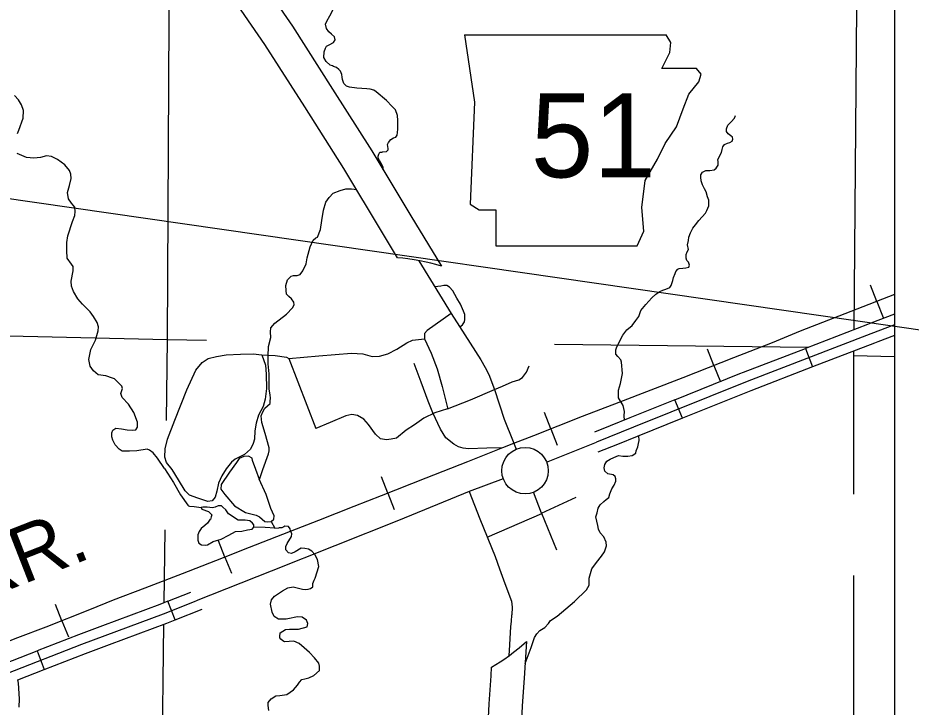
# Model space of a CAD drawing. Extents: x 8749 to 11879, y 13275 to 15339.
# Drawn here: x 10827.5 to 10962.2, y 13800.6 to 13904.5 of the extents above; entities that cross this region are included whole.
import ezdxf

# ---------------------------------------------------------------- set-up
doc = ezdxf.new("R2010")
doc.units = 0
for name, color, linetype in [('Level 10', 7, 'Continuous'), ('Level 21', 7, 'Continuous'), ('Level 22', 7, 'Continuous'), ('Level 24', 7, 'Continuous'), ('Level 31', 7, 'Continuous'), ('Level 32', 7, 'Continuous'), ('Level 35', 7, 'Continuous'), ('Level 4', 7, 'Continuous'), ('Level 40', 7, 'Continuous'), ('Level 5', 7, 'Continuous'), ('R_Draft', 7, 'Continuous')]:
    doc.layers.add(name, color=color, linetype=linetype)

msp = doc.modelspace()

# ---------------------------------------------------------------- linework, layer by layer
at = {"layer": 'Level 10'}
for points in [[(10863.29, 13911.43), (10868.9, 13903.24), (10874.98, 13893.76), (10880.91, 13884.42), (10886.77, 13874.66), (10891.41, 13867.06)], [(10884.78, 13868.31), (10882.49, 13872.07), (10876.65, 13881.8), (10870.77, 13891.08), (10864.73, 13900.47), (10859.16, 13908.61)], [(10891.41, 13867.06), (10890.52, 13867.31), (10889.81, 13867.49), (10889.08, 13867.66), (10888.14, 13867.85), (10887.28, 13868), (10886.33, 13868.14), (10885.54, 13868.24), (10884.78, 13868.31)], [(10887.98, 13867.88), (10892.85, 13859.9), (10894.12, 13857.97), (10897.32, 13852.91), (10897.97, 13851.76), (10898.52, 13850.74), (10899.41, 13848.44), (10900.85, 13843.99), (10902.2, 13840.61), (10902.47, 13839.98), (10902.68, 13839.46)], [(10900.72, 13835), (10895.59, 13833.08)], [(10895.59, 13833.08), (10897.18, 13828.98), (10899.49, 13823.3), (10900.14, 13821.45), (10900.74, 13819.78), (10901.26, 13818.4), (10901.95, 13816.57), (10902.07, 13815.66), (10902, 13814.51)], [(10901.58, 13808.33), (10901.68, 13809.97), (10901.86, 13812.73), (10901.94, 13813.49), (10902, 13814.51)], [(10898.96, 13806.6), (10899.61, 13807.01), (10900.26, 13807.42), (10900.79, 13807.78), (10901.63, 13808.37), (10902.28, 13808.87), (10903.09, 13809.51), (10904.22, 13810.47)], [(10904.22, 13810.47), (10903.86, 13804.97), (10903.58, 13800.79), (10903.29, 13794.78), (10903.08, 13790.3), (10902.9, 13782.42), (10902.8, 13776.62)], [(10897.8, 13776.71), (10897.9, 13782.52), (10898.09, 13790.48), (10898.3, 13795.02), (10898.59, 13801.08), (10898.87, 13805.3), (10898.96, 13806.6)]]:
    msp.add_lwpolyline(points, dxfattribs=at)
at = {"layer": 'Level 21'}
for p, q in [((10894.86, 13901.94), (10896.39, 13891.79)), ((10925.99, 13900.76), (10925.29, 13901.93)), ((10925.82, 13899.24), (10925.99, 13900.76)), ((10924.64, 13896.87), (10925.82, 13899.24)), ((10929.88, 13896.87), (10924.64, 13896.87)), ((10930.56, 13896.02), (10929.88, 13896.87)), ((10930.22, 13894.84), (10930.56, 13896.02)), ((10928.7, 13892.98), (10930.22, 13894.84)), ((10927.85, 13890.78), (10928.7, 13892.98)), ((10896.39, 13891.79), (10895.71, 13876.4)), ((10926.84, 13888.07), (10927.85, 13890.78)), ((10925.15, 13885.53), (10926.84, 13888.07)), ((10923.96, 13883.16), (10925.15, 13885.53)), ((10922.1, 13879.95), (10923.96, 13883.16)), ((10921.59, 13875.89), (10922.1, 13879.95)), ((10895.71, 13876.4), (10897.06, 13875.55)), ((10897.06, 13875.55), (10899.6, 13875.55)), ((10899.6, 13875.55), (10899.6, 13870.14)), ((10921.93, 13872.34), (10921.59, 13875.89)), ((10920.92, 13870.14), (10921.93, 13872.34)), ((10899.6, 13870.14), (10920.92, 13870.14))]:
    msp.add_line(p, q, dxfattribs=at)
msp.add_lwpolyline([(10894.86, 13901.94), (10925.29, 13901.93)], dxfattribs=at)
at = {"layer": 'Level 22'}
msp.add_lwpolyline([(10959.72, 13858.22), (10956.18, 13856.86), (10937.5, 13849.67), (10920.37, 13842.78), (10914.78, 13840.54)], dxfattribs=at)
at = {"layer": 'Level 24'}
msp.add_circle((10904, 13836.22), 3.5, dxfattribs=at)
at = {"layer": 'Level 31'}
for p, q in [((10946.28, 13854.66), (10947.36, 13851.86)), ((10927.73, 13844.12), (10926.61, 13846.91)), ((10851.23, 13813.74), (10850.13, 13816.53)), ((10850.13, 13816.53), (10850.13, 13816.53)), ((10830.39, 13809.05), (10831.47, 13806.25))]:
    msp.add_line(p, q, dxfattribs=at)
for points in [[(10959.72, 13859.82), (10956.14, 13858.45)], [(10956.14, 13858.45), (10955.64, 13858.26), (10946.28, 13854.66)], [(10959.72, 13856.61), (10957.21, 13855.65)], [(10957.21, 13855.65), (10956.72, 13855.46), (10947.36, 13851.86)], [(10936.41, 13850.85), (10936.95, 13851.06), (10946.28, 13854.66)], [(10926.61, 13846.91), (10936.41, 13850.85)], [(10947.36, 13851.86), (10938.05, 13848.27), (10937.53, 13848.06)], [(10926.61, 13846.91), (10919.82, 13844.17), (10916.82, 13842.97)], [(10937.53, 13848.06), (10927.73, 13844.12)], [(10927.73, 13844.12), (10920.93, 13841.39), (10917.93, 13840.19)], [(10916.82, 13842.97), (10914.5, 13842.04)], [(10907.25, 13837.52), (10914.78, 13840.54)], [(10917.93, 13840.19), (10914.99, 13839.01)], [(10895.59, 13833.08), (10884.89, 13828.72), (10865.69, 13821.07), (10854.39, 13816.6)], [(10906.49, 13829.81), (10905.27, 13832.96)], [(10898.31, 13826.2), (10906.51, 13829.76)], [(10850.13, 13816.53), (10853.57, 13817.89)], [(10825.81, 13805.66), (10837.15, 13810.07), (10849.45, 13814.65), (10854.39, 13816.6)], [(10850.13, 13816.53), (10848.91, 13816.05), (10840.27, 13812.83)], [(10851.23, 13813.74), (10855.28, 13815.34)], [(10841.32, 13810.02), (10849.99, 13813.25), (10851.23, 13813.74)], [(10840.27, 13812.83), (10836.62, 13811.47), (10830.39, 13809.05)], [(10824.71, 13800.69), (10824.75, 13801.81), (10824.63, 13803.82), (10824.1, 13806.61), (10830.39, 13809.05)], [(10831.47, 13806.25), (10837.68, 13808.67), (10841.32, 13810.02)], [(10827.71, 13800.58), (10827.75, 13801.85), (10827.61, 13804.19), (10827.51, 13804.71), (10831.47, 13806.25)]]:
    msp.add_lwpolyline(points, dxfattribs=at)
at = {"layer": 'Level 32'}
for points in [[(10894.14, 13857.93), (10894.56, 13858.22), (10894.85, 13858.64), (10894.92, 13859.02), (10894.9, 13859.77), (10894.74, 13860.28), (10894.28, 13861.33), (10893.72, 13862.22), (10893.12, 13863.31), (10892.61, 13863.91), (10892.21, 13864.13), (10891.77, 13864.13), (10891.3, 13864.02), (10890.38, 13863.95)], [(10892.85, 13859.9), (10889.25, 13857.38), (10888.85, 13856.89), (10888.81, 13856.09), (10889.83, 13853.96), (10890.76, 13851.56), (10891.52, 13848.89), (10892.36, 13845.51)], [(10868.39, 13853.13), (10872.87, 13853.53), (10877.8, 13853.93), (10879.54, 13853.84), (10880.96, 13853.44), (10882.07, 13853.49), (10883.28, 13853.86), (10884.64, 13854.55), (10886.15, 13855.49), (10887, 13855.89), (10887.93, 13855.98), (10888.81, 13856.09)], [(10864.3, 13853.7), (10864.83, 13852.15), (10864.97, 13850.77), (10865.01, 13848.6), (10864.79, 13847), (10864.48, 13845.88), (10863.77, 13844.59), (10863.46, 13843.39), (10863.23, 13842.24), (10863.19, 13840.95), (10863.01, 13840.33), (10862.61, 13839.48), (10861.68, 13838.64), (10860.3, 13837.97), (10859.73, 13837.53), (10858.93, 13836.5), (10858.26, 13835.44), (10857.77, 13834.32), (10857.51, 13833.12), (10857.24, 13832.23), (10856.79, 13831.66), (10856.17, 13831.57), (10854.62, 13832.06), (10853.37, 13832.55), (10852.71, 13833.21), (10851.73, 13834.86), (10850.75, 13836.41), (10849.91, 13837.44), (10849.69, 13838.28), (10849.73, 13839.53), (10850.09, 13840.99), (10851.15, 13843.84), (10852.97, 13848.42), (10854.35, 13851.4), (10855.28, 13852.51), (10856.22, 13853.13), (10857.46, 13853.44), (10858.93, 13853.71), (10861.1, 13853.8), (10863.01, 13853.84), (10864.3, 13853.7)], [(10864.3, 13853.7), (10866.3, 13853.58), (10868.03, 13853.35), (10868.39, 13853.13), (10871.1, 13846.11), (10872.42, 13842.59)], [(10899.41, 13848.44), (10900.62, 13848.96), (10902.08, 13849.6), (10903.06, 13849.94), (10903.61, 13850.28), (10904.2, 13851.08), (10904.64, 13852.04)], [(10892.32, 13845.54), (10895.78, 13846.89), (10899.41, 13848.44)], [(10892.32, 13845.54), (10890.41, 13844.95), (10888.75, 13844.12), (10887.34, 13843.13), (10886.06, 13842.33), (10884.59, 13841.13), (10883.79, 13840.95), (10883.08, 13840.86), (10882.19, 13841.04), (10881.44, 13841.75), (10880.37, 13843.17), (10879.66, 13843.97), (10878.73, 13844.55), (10877.88, 13844.68), (10876.99, 13844.51), (10874.6, 13843.48), (10872.42, 13842.59)], [(10906.49, 13829.8), (10911.71, 13832.21)], [(10906.49, 13829.8), (10908.75, 13824.3)]]:
    msp.add_lwpolyline(points, dxfattribs=at)
at = {"layer": 'Level 35'}
for points in [[(10874.43, 13900.41), (10875.11, 13900.77), (10875.34, 13901.17), (10875.26, 13901.6), (10874.81, 13902.01), (10874.38, 13902.36), (10874.03, 13902.89), (10873.92, 13903.55), (10874.08, 13904.01), (10874.53, 13904.81), (10875.11, 13905.85), (10875.84, 13906.79), (10876.85, 13908.18), (10877.11, 13908.76), (10877.18, 13909.34)], [(10884.79, 13887.72), (10884.81, 13889.03), (10884.74, 13889.76), (10884.46, 13890.62), (10883.95, 13891.1), (10883.12, 13892.04), (10881.55, 13893.33), (10881.17, 13893.58), (10880.62, 13893.76), (10880.14, 13893.81), (10878.62, 13893.91), (10877.51, 13894.03), (10877.08, 13894.21), (10876.65, 13894.59), (10876.48, 13895.17), (10876.43, 13895.53), (10876.37, 13895.93), (10876.17, 13896.44), (10875.9, 13896.69), (10875.57, 13897.02), (10875.12, 13897.13), (10874.94, 13897.25), (10874.58, 13897.37), (10873.98, 13897.9), (10873.67, 13898.53), (10873.7, 13899.34), (10873.9, 13899.9), (10874.05, 13900.2), (10874.43, 13900.41)], [(10827.46, 13887.04), (10827.63, 13887.55), (10828.32, 13889.37), (10828.34, 13890.54), (10828.04, 13891.37), (10827.58, 13892.13), (10827, 13892.77)], [(10934.06, 13885.39), (10934.54, 13885.58), (10934.89, 13885.69), (10935.22, 13885.89), (10935.34, 13886.19), (10935.29, 13886.49), (10935.04, 13886.72), (10934.64, 13887), (10934.41, 13887.35), (10934.36, 13887.76), (10934.61, 13888.29), (10935.09, 13888.8), (10935.57, 13889.35), (10935.72, 13889.78)], [(10882.38, 13882.36), (10882.03, 13882.97), (10881.83, 13883.35), (10881.83, 13883.65), (10881.93, 13883.93), (10882.08, 13884.26), (10882.46, 13884.26), (10882.51, 13884.28), (10883.09, 13884.33), (10883.37, 13884.61), (10883.37, 13884.81), (10883.32, 13885.09), (10883.27, 13885.4), (10883.4, 13885.72), (10883.73, 13886.15), (10884.18, 13886.38), (10884.51, 13886.48), (10884.71, 13886.79), (10884.76, 13887.19), (10884.79, 13887.72)], [(10930.72, 13874.49), (10931.23, 13875.05), (10931.4, 13875.43), (10931.73, 13876.16), (10931.71, 13877), (10931.53, 13877.53), (10931.33, 13878.24), (10931.08, 13878.72), (10930.75, 13879.32), (10930.57, 13879.93), (10930.52, 13880.46), (10930.52, 13880.84), (10930.77, 13881.24), (10931.25, 13881.47), (10931.88, 13881.5), (10932.51, 13881.57), (10932.82, 13881.83), (10933.12, 13882.28), (10933.15, 13882.79), (10933.1, 13883.14), (10933.27, 13883.49), (10933.42, 13883.85), (10933.63, 13884.18), (10933.75, 13884.66), (10933.83, 13885.06), (10934.06, 13885.39)], [(10836.16, 13875.31), (10836.09, 13875.97), (10835.58, 13876.53), (10835.13, 13877.21), (10835, 13878.17), (10835.3, 13879.21), (10835.53, 13880.28), (10835.5, 13880.94), (10835.28, 13881.49), (10834.57, 13882.35), (10833.48, 13883.14), (10832.57, 13883.6), (10831.83, 13883.7), (10830.92, 13883.44), (10829.91, 13883.34), (10828.82, 13883.44), (10827.38, 13884.05)], [(10882.61, 13881.59), (10882.59, 13881.94), (10882.38, 13882.36)], [(10872.71, 13871.45), (10873.14, 13872.59), (10873.34, 13873.93), (10873.6, 13875.5), (10873.95, 13876.69), (10874.46, 13877.42), (10875.06, 13878.05), (10876.12, 13878.48), (10876.98, 13878.73), (10877.84, 13878.71), (10878.57, 13878.6)], [(10835.54, 13864.81), (10835.83, 13866.36), (10835.83, 13867), (10835.61, 13867.35), (10834.95, 13868.26), (10834.9, 13869.43), (10834.87, 13870.6), (10835.02, 13871.61), (10835.76, 13873.79), (10836.11, 13874.7), (10836.16, 13875.31)], [(10921.15, 13859.46), (10921.48, 13860.36), (10922.21, 13861.27), (10923.14, 13862.28), (10923.72, 13862.81), (10924.31, 13863.24), (10924.76, 13863.44), (10925.22, 13863.59), (10925.85, 13863.84), (10926.02, 13864.12), (10926.28, 13864.91), (10926.4, 13865.34), (10926.63, 13865.94), (10926.73, 13866.27), (10927.03, 13866.58), (10927.26, 13866.7), (10927.79, 13866.75), (10928.27, 13866.78), (10928.68, 13866.9), (10928.78, 13867.18), (10928.65, 13867.64), (10928.42, 13867.91), (10928.32, 13868.24), (10928.32, 13868.83), (10928.45, 13869.23), (10928.63, 13869.56), (10928.52, 13870.29), (10928.63, 13870.9), (10928.68, 13871.43), (10928.93, 13872.09), (10929.33, 13872.77), (10929.69, 13873.27), (10930.19, 13873.93), (10930.72, 13874.49)], [(10868.18, 13864.98), (10868.74, 13865.54), (10869.07, 13865.67), (10869.65, 13865.67), (10870.08, 13865.82), (10870.49, 13866.35), (10870.97, 13867.39), (10871.12, 13868.3), (10871.6, 13869.97), (10872.06, 13870.96), (10872.44, 13871.31), (10872.71, 13871.45)], [(10839.61, 13857.29), (10839.66, 13857.91), (10839.45, 13858.55), (10838.9, 13859.48), (10838.4, 13860.16), (10837.81, 13860.77), (10837.26, 13861.34), (10836.55, 13862.11), (10835.89, 13863.21), (10835.61, 13864.05), (10835.54, 13864.81)], [(10868.01, 13859.83), (10868.92, 13860.78), (10869.15, 13861.23), (10869.12, 13861.64), (10868.77, 13862.14), (10868.36, 13862.47), (10868.03, 13862.85), (10867.98, 13863.41), (10867.93, 13864.12), (10868.18, 13864.98)], [(10863.96, 13834.9), (10864.46, 13836.41), (10865.32, 13838.74), (10865.38, 13839.2), (10865.4, 13839.68), (10864.79, 13841.81), (10864.31, 13843.48), (10864.19, 13844.49), (10864.46, 13845.1), (10864.74, 13845.66), (10865.53, 13846.37), (10865.55, 13846.72), (10865.58, 13847.13), (10865.55, 13847.66), (10865.4, 13848.52), (10865.38, 13848.82), (10865.4, 13850.84), (10865.25, 13852.33), (10865.25, 13853.5), (10865.32, 13854.92), (10865.63, 13856.31), (10865.58, 13857.14), (10865.63, 13857.78), (10866.26, 13858.46), (10868.01, 13859.83)], [(10918.4, 13849.37), (10918.7, 13850.89), (10918.55, 13852.58), (10918.43, 13852.91), (10917.97, 13853.42), (10917.69, 13853.8), (10917.67, 13854.2), (10917.67, 13854.43), (10917.77, 13854.76), (10918, 13855.21), (10918.75, 13856.63), (10919.36, 13857.44), (10920.17, 13858.1), (10920.72, 13858.88), (10921.15, 13859.46)], [(10840.75, 13850.5), (10839.61, 13850.68), (10838.9, 13851.29), (10838.39, 13851.97), (10838.19, 13852.96), (10838.49, 13854.51), (10839.2, 13855.88), (10839.61, 13857.29)], [(10843.02, 13847.88), (10843.28, 13848.6), (10843.2, 13848.98), (10842.54, 13849.62), (10842.06, 13850.05), (10841.76, 13850.18), (10840.75, 13850.5)], [(10918.98, 13843.84), (10918.96, 13844.51), (10919.01, 13845.12), (10918.8, 13846.03), (10918.12, 13847.22), (10918.1, 13847.75), (10918.12, 13848.35), (10918.4, 13849.37)], [(10849.61, 13836.53), (10848.54, 13838.13), (10847.91, 13838.91), (10847.35, 13839.34), (10847, 13839.47), (10845.45, 13839.22), (10844.32, 13839.19), (10843.25, 13839.19), (10842.77, 13839.47), (10842.16, 13840.1), (10841.84, 13840.81), (10841.68, 13841.34), (10841.68, 13841.93), (10841.84, 13842.31), (10842.29, 13842.61), (10843.13, 13842.51), (10844.01, 13842.38), (10844.75, 13842.31), (10845.28, 13842.38), (10845.56, 13842.76), (10845.56, 13843.52), (10844.97, 13844.99), (10844.19, 13846.23), (10843.23, 13847.27), (10843.02, 13847.88)], [(10918.07, 13838.53), (10918.73, 13838.42), (10919.51, 13838.42), (10920.17, 13838.49), (10920.7, 13838.85), (10920.77, 13839.23), (10921, 13839.83), (10921.1, 13840.34), (10921.2, 13840.79), (10921.16, 13841.48)], [(10863.96, 13834.9), (10863.4, 13836.4), (10862.87, 13837.76), (10862.82, 13838.09), (10862.31, 13838.42), (10861.58, 13838.37), (10860.87, 13838.07), (10860.49, 13837.44), (10859.4, 13835.99), (10858.16, 13834.12), (10858.11, 13833.43), (10858.72, 13832.65), (10860.19, 13830.92), (10861.81, 13829.94), (10863.45, 13829.51), (10863.96, 13829.25), (10864.36, 13828.92), (10864.77, 13828.54), (10865.12, 13828.49), (10865.71, 13828.54), (10866.09, 13828.92), (10866.14, 13829.4), (10865.66, 13830.52), (10864.95, 13832.65), (10863.91, 13834.95)], [(10914.97, 13827.98), (10914.66, 13829.28), (10914.86, 13829.86), (10915.02, 13830.57), (10915.34, 13831.05), (10915.87, 13831.58), (10916.25, 13831.86), (10916.66, 13832.19), (10916.81, 13832.74), (10917.11, 13833.48), (10917.44, 13834.06), (10917.67, 13834.64), (10917.69, 13834.99), (10917.57, 13835.37), (10917.29, 13835.62), (10916.48, 13835.75), (10916.03, 13836.13), (10915.93, 13836.66), (10916.03, 13837.17), (10916.35, 13837.67), (10916.83, 13837.98), (10917.39, 13838.23), (10918.07, 13838.53)], [(10849.61, 13836.53), (10850.96, 13834.43), (10852.05, 13832.58), (10853.13, 13831.02)], [(10853.13, 13831.02), (10853.23, 13830.92), (10853.37, 13830.89)], [(10853.37, 13830.89), (10854.1, 13830.83), (10855.14, 13830.65)], [(10856.52, 13828.91), (10856.11, 13828.32), (10855.68, 13827.97), (10855.15, 13827.51), (10854.87, 13827.03), (10854.65, 13826.55), (10854.65, 13825.76), (10854.77, 13825.31), (10855.18, 13825.05), (10855.83, 13825), (10856.09, 13825.03), (10856.97, 13825.54), (10858.14, 13825.89), (10859.33, 13826.52), (10860.34, 13827.08), (10861.3, 13827.13), (10862.16, 13827.31), (10862.82, 13827.41), (10863.1, 13827.69), (10863.1, 13828.04), (10862.87, 13828.32), (10862.49, 13828.65), (10861.78, 13828.78), (10861.3, 13828.75), (10860.72, 13828.75), (10859.25, 13829.74), (10858.87, 13830.3), (10858.44, 13830.73), (10858.19, 13830.93), (10857.73, 13830.93), (10857.25, 13830.73), (10856.87, 13830.6), (10856.04, 13830.7), (10855.66, 13830.73), (10855.38, 13830.7), (10855.14, 13830.65), (10855.23, 13830.4), (10856.24, 13830.05), (10856.75, 13829.59), (10856.67, 13829.26), (10856.54, 13828.85)], [(10865.71, 13828.54), (10866.27, 13827.55)], [(10908.86, 13814.27), (10911.45, 13816.48), (10913.25, 13818.25), (10913.68, 13818.98), (10913.65, 13820.02), (10914.06, 13821.41), (10914.76, 13822.39), (10915.55, 13823.35), (10915.98, 13823.99), (10916.28, 13824.9), (10916.25, 13825.45), (10915.87, 13826.24), (10915.34, 13826.84), (10915.07, 13827.43), (10914.97, 13827.98)], [(10866.27, 13827.55), (10864.82, 13827.68), (10863.1, 13827.69)], [(10866.27, 13827.55), (10866.84, 13827.59)], [(10872.34, 13820), (10872.89, 13821.76), (10872.71, 13822.85), (10872.31, 13823.61), (10872.31, 13823.61), (10871.85, 13824.09), (10871.35, 13824.4), (10870.79, 13824.47), (10870.21, 13824.52), (10869.32, 13823.99), (10868.79, 13823.76), (10868.31, 13823.86), (10867.93, 13824.29), (10867.9, 13824.8), (10868.13, 13825.26), (10868.76, 13826.3), (10868.81, 13826.7), (10868.64, 13827.16), (10868.59, 13827.46), (10868.31, 13827.82), (10867.78, 13827.87), (10867.6, 13827.74), (10867.32, 13827.61), (10866.84, 13827.59)], [(10869.02, 13818.71), (10870.05, 13818.48), (10870.41, 13818.38), (10870.81, 13818.33), (10871.27, 13818.36), (10871.62, 13818.46), (10871.98, 13818.71), (10872, 13819.24), (10872.18, 13819.72), (10872.34, 13820)], [(10867.04, 13811.8), (10867.85, 13812.28), (10868.49, 13812.33), (10869.85, 13812.33), (10871.14, 13812.68), (10871.24, 13813.21), (10871.04, 13813.67), (10870.36, 13814.12), (10869.68, 13814.18), (10868.23, 13813.9), (10867.95, 13813.82), (10867.42, 13813.82), (10866.79, 13813.85), (10866.16, 13814.25), (10865.85, 13814.88), (10865.6, 13816.08), (10865.75, 13816.73), (10866.23, 13817.32), (10867.4, 13818.1), (10868.23, 13818.56), (10869.02, 13818.71)], [(10904, 13807.14), (10904.92, 13809.59), (10905.4, 13811.06), (10905.78, 13811.62), (10906.21, 13812.15), (10906.97, 13812.6), (10907.55, 13813.18), (10907.85, 13813.66), (10908.86, 13814.27)], [(10865.35, 13800.09), (10865.27, 13800.83), (10865.27, 13801.26), (10865.73, 13801.81), (10866.41, 13802.29), (10867.02, 13802.34), (10868.08, 13802.49), (10869.09, 13803.18), (10869.67, 13803.88), (10869.97, 13804.36), (10870.33, 13804.72), (10870.78, 13804.87), (10871.41, 13805), (10872.14, 13805.33), (10872.98, 13806.11), (10873, 13806.77), (10872.9, 13807.2), (10872.25, 13808.03), (10871.49, 13808.81), (10870.7, 13809.52), (10869.95, 13810.15), (10869.14, 13810.53), (10867.72, 13810.41), (10867.45, 13810.58), (10867.14, 13810.84), (10866.99, 13811.04), (10866.99, 13811.22), (10867.04, 13811.8)]]:
    msp.add_lwpolyline(points, dxfattribs=at)
at = {"layer": 'Level 4'}
for points in [[(10954.46, 13960.92), (10953.57, 13857.46)], [(10953.55, 13854.24), (10953.55, 13853.6), (10953.53, 13832.7)], [(10953.53, 13820.42), (10953.48, 13747.58), (10953.48, 13747.19), (10951.54, 13643.03), (10951.54, 13642.23), (10951.1, 13546.98)]]:
    msp.add_lwpolyline(points, dxfattribs=at)
at = {"layer": 'Level 40'}
for p, q in [((10957.05, 13861.75), (10956.09, 13864.2)), ((10957.05, 13861.75), (10958.02, 13859.29)), ((10932.49, 13852.07), (10931.53, 13854.52)), ((10932.49, 13852.07), (10933.46, 13849.61)), ((10907.88, 13842.52), (10906.91, 13844.97)), ((10907.88, 13842.52), (10908.86, 13840.06)), ((10883.32, 13832.85), (10882.36, 13835.31)), ((10883.32, 13832.85), (10884.28, 13830.39)), ((10858.74, 13823.21), (10857.78, 13825.67)), ((10858.74, 13823.21), (10859.7, 13820.75)), ((10834.15, 13813.61), (10833.17, 13816.07)), ((10834.15, 13813.61), (10835.12, 13811.16))]:
    msp.add_line(p, q, dxfattribs=at)
for points in [[(10959.72, 13862.8), (10953.14, 13860.2), (10945.49, 13857.24), (10941.28, 13855.51), (10935.45, 13853.23), (10927.82, 13850.23), (10918.14, 13846.52), (10912.62, 13844.4), (10905.28, 13841.48), (10902.26, 13840.33), (10900.62, 13839.68), (10895.33, 13837.56), (10889.03, 13835.08), (10882.31, 13832.45), (10878.19, 13830.83), (10872.84, 13828.71), (10868.58, 13827.07), (10861.22, 13824.18), (10859.37, 13823.46), (10852.26, 13820.69), (10846.63, 13818.51), (10841.88, 13816.68), (10838.3, 13815.27), (10831.74, 13812.65), (10827.46, 13811.01)], [(10959.72, 13862.8), (10953.14, 13860.2)], [(10953.14, 13860.2), (10945.49, 13857.24), (10941.28, 13855.51), (10935.45, 13853.23), (10927.82, 13850.23), (10918.14, 13846.52), (10912.62, 13844.4), (10905.28, 13841.48), (10902.26, 13840.33), (10900.62, 13839.68), (10895.33, 13837.56), (10889.03, 13835.08), (10882.31, 13832.45), (10878.19, 13830.83), (10872.84, 13828.71), (10868.58, 13827.07), (10861.22, 13824.18), (10859.37, 13823.46)], [(10900.62, 13839.68), (10898.24, 13839.63), (10895.49, 13839.52), (10894.68, 13839.63), (10893.96, 13839.81), (10893.24, 13840.22), (10892.06, 13841.16), (10891.23, 13842.49), (10890.11, 13844.95), (10889.39, 13846.71), (10888.33, 13849.57), (10887.29, 13852.39)], [(10859.37, 13823.46), (10852.26, 13820.69), (10846.63, 13818.51), (10841.88, 13816.68), (10838.3, 13815.27), (10831.74, 13812.65), (10827.46, 13811.01), (10822.33, 13809.01), (10816.86, 13806.89), (10810.58, 13804.39), (10802.93, 13801.42), (10796.47, 13798.86), (10788.36, 13795.61), (10780.59, 13792.6), (10775.27, 13790.5), (10767.78, 13787.44), (10759.38, 13784.15), (10753.12, 13781.63), (10747, 13779.26)]]:
    msp.add_lwpolyline(points, dxfattribs=at)
at = {"layer": 'Level 5'}
for points in [[(10850.48, 13943.03), (10850, 13855.98)], [(10743.61, 13858.47), (10850, 13855.98)], [(10850, 13855.98), (10849.86, 13843.81)], [(10850, 13855.98), (10855.97, 13855.91)], [(10908.45, 13855.28), (10946.73, 13854.83)], [(10953.55, 13853.6), (10959.72, 13853.46)], [(10849.66, 13827.33), (10849.52, 13816.3)], [(10849.48, 13813.07), (10848.7, 13748.87)]]:
    msp.add_lwpolyline(points, dxfattribs=at)
at = {"layer": 'R_Draft'}
msp.add_line((11054.48, 13844.3), (10330.62, 13948.56), dxfattribs=at)
msp.add_lwpolyline([(9678.09, 14456.3), (10959.72, 14456.3), (10959.72, 13439.87), (9678.09, 13439.87)], close=True, dxfattribs=at)

# ---------------------------------------------------------------- texts
at = {"layer": 'Level 21'}
msp.add_text('51', height=12.672, dxfattribs=at).set_placement((10904.87, 13880.44))
at = {"layer": 'Level 40'}
msp.add_text('UNION PACIFIC RR.', height=8.448, rotation=21.3423, dxfattribs=at).set_placement((10739.39, 13784.33))

doc.saveas('drawing.dxf')
